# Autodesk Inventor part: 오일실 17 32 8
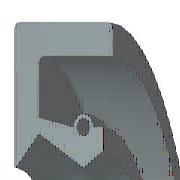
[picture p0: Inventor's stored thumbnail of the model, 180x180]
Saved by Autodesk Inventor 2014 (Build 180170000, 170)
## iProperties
IsCustomPart: 1
Created: 2012-02
Part Number: 오일실 17 32 8
Material: 고무
Description: 오일-실
Document SubType Name: Modeling
Standard: KS B 2804
Designer: mduedu
Standards Organization: KS
Language: ko-KR
Size Designation: D - 17 32 8
Categories: <MemberInstance><Categories><Category DisplayName="샤프트 부품" InternalName="7f7aeb1f-a693-4053-b835-cee3144e0d98" Mnemonic="SHFT"><Category DisplayName="실링" Intern
Density: 0.93 g/cm^3
Appearance: 고무 - 검은색 - 버전 1.1
Author: mduedu
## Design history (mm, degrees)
revolve "본체" stored, may be unused: angle "d17" = 90 deg
revolve "스프링1" stored, may be unused: angle "d18" = 90 deg
body "Solid1"
sketch "스케치1"
  geometry: L1 (0, 16)-(8, 16); L2 (8, 14.25)-(1.75, 14.25); L3 (1.75, 10.25)-(4.9, 8.5); L4 (4.9, 8.5)-(0, 8.5); L5 (0, 0)-(9.586, 0) reference; L6 (4.9, 8.5)-(6.3, 9.375); L7 (0, 18)-(0, -3) reference; L8 (-1.941, 0)-(11.507, 0) reference; L9 (4.2, 10.6)-(1.75, 11.21); L10 (1.75, 11.21)-(1.75, 14.25); L11 (0, 16)-(0, 8.588); L12 (4.9, 8.5)-(0, 8.5); L13 (1.75, 10.25)-(0.152, 8.528); L14 (8, 16)-(8, 14.25); L15 (5.6, 10.6)-(6.3, 10.6); L16 (6.3, 10.6)-(6.3, 9.375); C1 r 0.455 at (4.9, 10.6); A1 r 0.7 centre (4.9, 10.6) between (5.6, 10.6) and (4.2, 10.6); A2 r 0.088 centre (0.088, 8.588) between (0, 8.588) and (0.152, 8.528); 1 further point
  constraints: 28 end point, 5 horizontal alignment, 5 point on line, 4 point on circle, 4 vertical alignment, 3 centre point, 3 tangent, 2 collinear, 2 horizontal, 2 perpendicular, 1 coincident, 1 parallel
  dimensions: "d0" = 32 diameter of L1 L5 (= SD2); "d1" = 1.75 distance of L1.end L2.start (= SD); "d2" = 0.91 diameter of C1 (= SPDI); "d3" = 1.4 diameter of A1 (= SPDA); "d4" = 17 diameter of L3.end L5 (= NND); "d5" = 20.5 diameter of L3.start L5 (= TKDM); "d7" = 22.42 diameter of L9.end L5 (= TKDM + 0.24 x SWDT); "d8" = 1.75 distance between parallel lines of L11 L10 (= SD); "d9" = 4.9 distance from line of L11 C1.centre (= SPDST); "d10" = 21.2 diameter of C1.centre L5 (= HLDM); "d11" = 0.0875 radius of A2 (= 0.25 x LAB); "d12" = 6.3 distance between parallel lines of L11 L16 (= SDI); "d13" = 18.75 diameter of L6.end L5 (= ABDM); "d14" = 8 distance from line of L11 L1.end (= SWDT)
fillet "모깎기1" dims "d6" = 0.3 (= RR)
other parameters: "SD2" = 32 [user parameter; used in 1 equation term], "SWDT" = 8 [user parameter; used in 2 equation terms], "RR" = 0.3 [user parameter; used in 1 equation term], "SD" = 1.75 [user parameter; used in 2 equation terms], "NND" = 17 [user parameter; used in 1 equation term], "SPDA" = 1.4 [user parameter; used in 1 equation term], "SPDI" = 0.91 [user parameter; used in 1 equation term], "TKDM" = 20.5 [user parameter; used in 2 equation terms], "HLDM" = 21.2 [user parameter; used in 1 equation term], "ABDM" = 18.75 [user parameter; used in 1 equation term], "SDI" = 6.3 [user parameter; used in 1 equation term], "SPDST" = 4.9 [user parameter; used in 1 equation term], "LAB" = 0.35 [user parameter; used in 1 equation term], "d15" = 0, "d16" = 0, "d19" = 0
